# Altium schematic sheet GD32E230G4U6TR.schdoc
size 127 x 101 mm
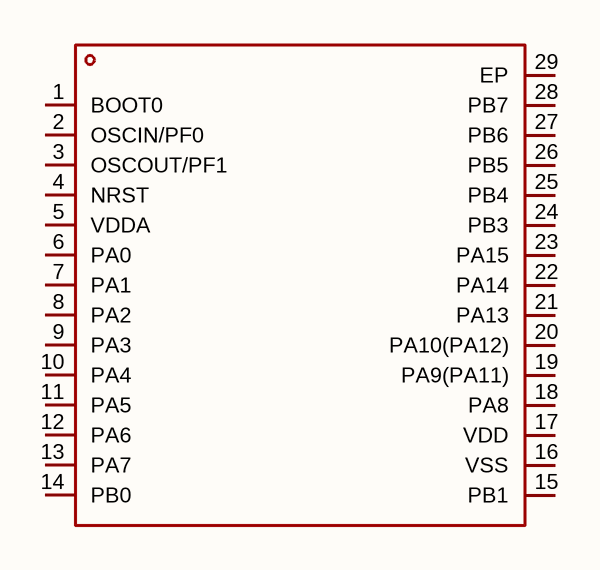
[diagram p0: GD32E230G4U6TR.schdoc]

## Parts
U?  gd32e230g4u6tr  [QFN-28_L4.0-W4.0-P0.40-BL-EP]  (value not drawn)

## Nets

Not connected (* = marked no-connect by the designer): U? 1(BOOT0) 2(OSCIN/PF0) 3(OSCOUT/PF1) 4(NRST) 5(VDDA) 6(PA0) 7(PA1) 8(PA2) 9(PA3) 10(PA4) 11(PA5) 12(PA6) 13(PA7) 14(PB0) 15(PB1) 16(VSS) 17(VDD) 18(PA8) 19(PA9(PA11)) 20(PA10(PA12)) 21(PA13) 22(PA14) 23(PA15) 24(PB3) 25(PB4) 26(PB5) 27(PB6) 28(PB7) 29(EP)

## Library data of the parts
U? = gd32e230g4u6tr: CPU内核:ARM Cortex-M系列;CPU最大主频:72MHz;; Manufacturer: GigaDevice(兆易创新); AddInBom: yes; ModelId: 11f4b67ac5604b8a9b305e4266e81461; ModelName: QFN-28_L4.0-W4.0-H0.9-P0.40-BL-EP; ModelTransform: 157.48,157.48,0,90,0,0,0,0,0; CPU Maximum Speed: 72MHz; Program Storage Size: 16KB; Program Memory Type: FLASH; Number of I/O: 23; ADC (Bit): 12bit; Voltage - Supply: 1.8V~3.6V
